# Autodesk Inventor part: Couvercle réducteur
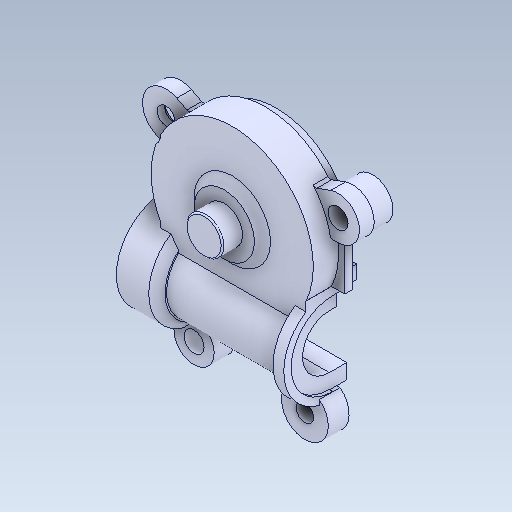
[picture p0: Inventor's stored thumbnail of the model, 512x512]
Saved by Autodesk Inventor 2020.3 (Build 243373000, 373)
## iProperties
Created: 2019-01
Part Number: Couvercle réducteur
Material: Générique
Document SubType Name: Modeling
Designer: ficho
Density: 1 g/cm^3
Appearance: Par défaut
Mass: 2.34852 g
Surface Area: 35.5421 cm^2
Volume: 2.34852 cm^3
Sending System: SolidWorks 2015
Last Author: adrien
Last Saved: 2019-01-11
Author: ficho
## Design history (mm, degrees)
feature "Boss.-Extru.6"
node "Solide1"
